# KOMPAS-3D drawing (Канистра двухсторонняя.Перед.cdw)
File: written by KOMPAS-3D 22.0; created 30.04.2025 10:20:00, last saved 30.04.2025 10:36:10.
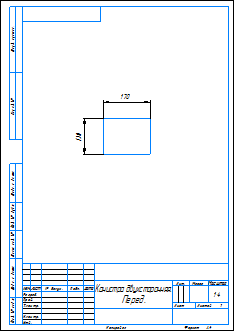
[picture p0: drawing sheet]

Sheet 1: A4, portrait

Document properties: Автор: Admin; Наименование: Канистра двухсторонняя. Перед; Полное имя файла: D:\28.11.2016\3D модели\Абилимпикс\2025\Канистра двухсторонняя\Канистра двухсторонняя.Перед.cdw

Title block, sheet 1: Наименование: Канистра двухсторонняя. / Перед.; scale: 1:4; Количество листов документа: 1; Форматы листов документа: A4; stored path: D:\28.11.2016\3D модели\Абилимпикс\2025\Канистра двухсторонняя\Канистра двухсторонняя.Боковина.cdw

Dimensions and other numbers on the sheet: 170; 130; 1:4; 1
